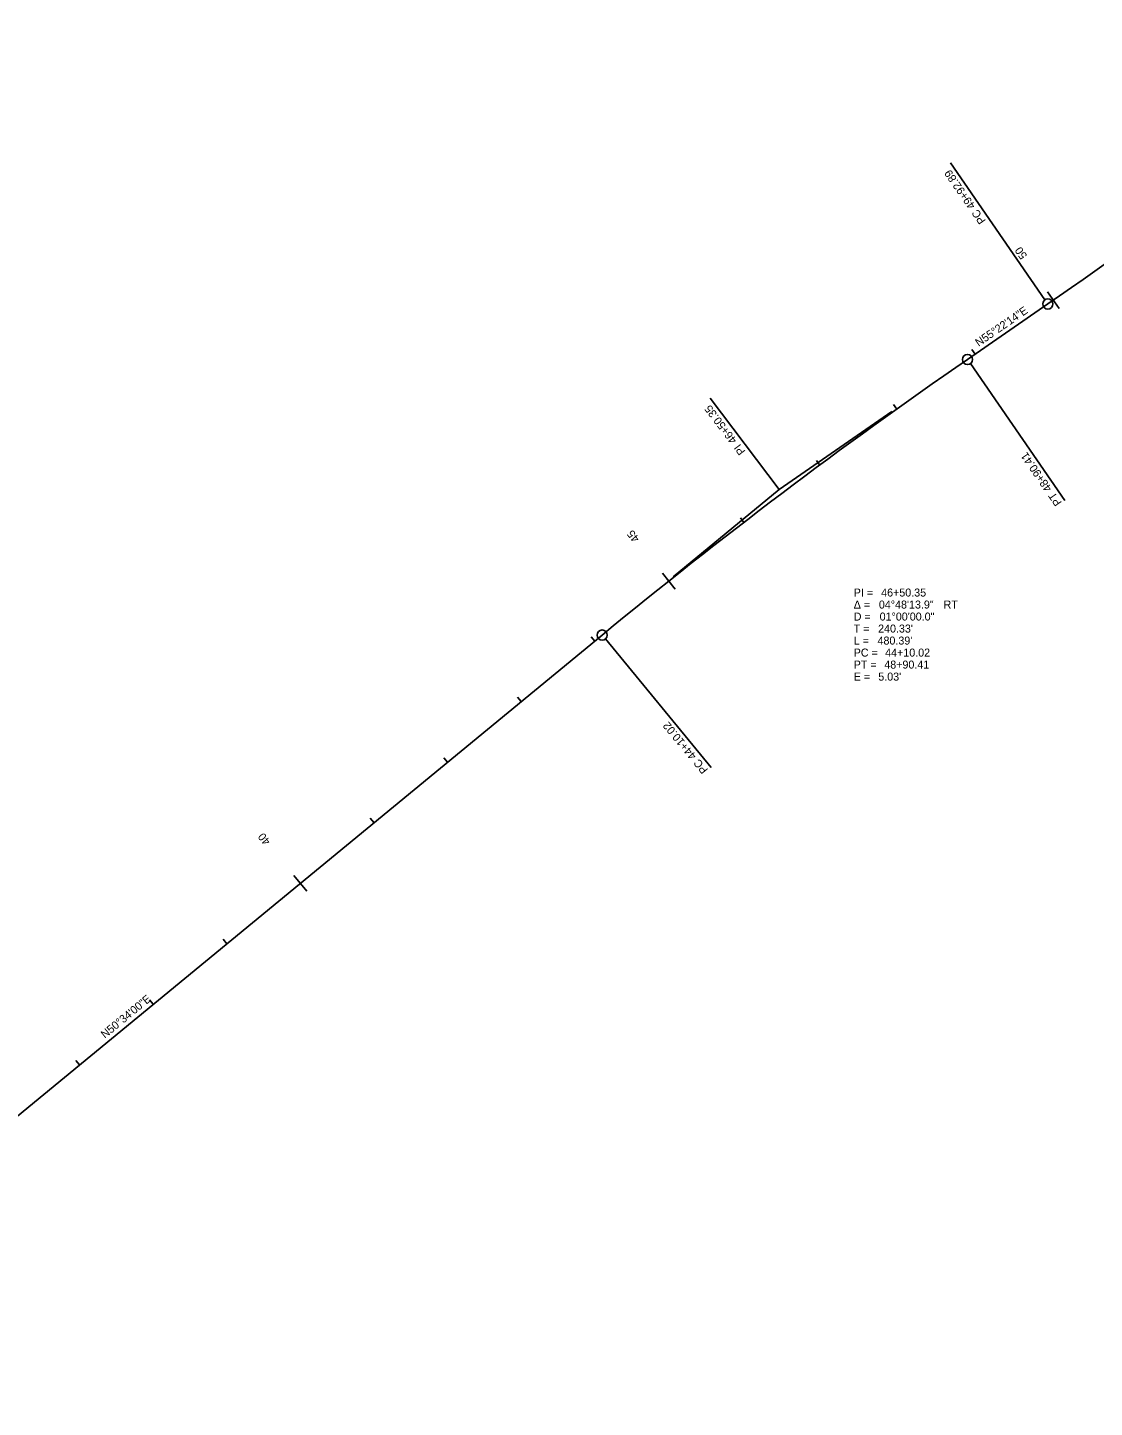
# Model space of a CAD drawing. Extents: x 1145421 to 1155673, y 2015317 to 2021442.
# Drawn here: x 1147223 to 1148342, y 2016869 to 2018317 of the extents above; entities that cross this region are included whole.
import ezdxf

# ---------------------------------------------------------------- set-up
doc = ezdxf.new("R2010")
doc.units = 0
for name, color, linetype in [('Default', 7, 'Continuous'), ('EX_CONTOUR_ANNOT_MINOR', 7, 'Continuous'), ('EX_TERRAIN', 7, 'Continuous')]:
    doc.layers.add(name, color=color, linetype=linetype)

msp = doc.modelspace()

# ---------------------------------------------------------------- linework, layer by layer
at = {"layer": 'Default'}
for p, q in [((1148208.9, 2017968.3), (1148293.2, 2018026.5)), ((1146840, 2016868.6), (1147825.5, 2017679.1))]:
    msp.add_line(p, q, dxfattribs=at)
for centre, start, end in [((1145037.3, 2022741.1), 304.62946, 309.44534), ((1151464.8, 2013253.8), 124.62946, 129.43332)]:
    msp.add_arc(centre, 5729.6, start, end, dxfattribs=at)
at = {"layer": 'EX_CONTOUR_ANNOT_MINOR'}
for p, q in [((1148290.2, 2018030.9), (1148190.9, 2018174.7)), ((1148190.9, 2018174.7), (1148190.9, 2018174.7)), ((1148293, 2018039.4), (1148305.1, 2018021.9)), ((1148293.2, 2018026.5), (1148293.2, 2018026.5)), ((1148213.4, 2017978.7), (1148216.8, 2017973.8)), ((1148208.9, 2017968.3), (1148208.9, 2017968.3)), ((1148211.9, 2017963.9), (1148311.2, 2017820.2)), ((1148011.1, 2017831.7), (1147938.9, 2017927.5)), ((1147938.9, 2017927.5), (1147938.9, 2017927.5)), ((1148011.1, 2017831.7), (1148129.6, 2017913.6)), ((1148131.4, 2017921.2), (1148134.9, 2017916.3)), ((1148050.5, 2017862.3), (1148054, 2017857.5)), ((1148011.1, 2017831.7), (1147899.9, 2017740.3)), ((1148311.2, 2017820.2), (1148311.2, 2017820.2)), ((1147970.6, 2017802.1), (1147974.2, 2017797.3)), ((1147888.8, 2017744), (1147902, 2017727.4)), ((1147814, 2017677.3), (1147817.8, 2017672.7)), ((1147825.5, 2017679.1), (1147825.5, 2017679.1)), ((1147828.9, 2017675), (1147939.8, 2017540.1)), ((1147736.7, 2017613.8), (1147740.5, 2017609.2)), ((1147659.5, 2017550.3), (1147663.3, 2017545.7)), ((1147939.8, 2017540.1), (1147939.8, 2017540.1)), ((1147582.2, 2017486.8), (1147586.1, 2017482.2)), ((1147502, 2017426.9), (1147515.5, 2017410.5)), ((1147427.8, 2017359.8), (1147431.6, 2017355.1)), ((1147350.5, 2017296.2), (1147354.4, 2017291.6)), ((1147273.3, 2017232.7), (1147277.1, 2017228.1))]:
    msp.add_line(p, q, dxfattribs=at)
for centre in [(1148293.2, 2018026.5), (1148208.9, 2017968.3), (1147825.5, 2017679.1)]:
    msp.add_circle(centre, 5.34, dxfattribs=at)
at = {"layer": 'EX_TERRAIN'}
for p, q in [((1148208.9, 2017968.3), (1148293.2, 2018026.5)), ((1146840, 2016868.6), (1147825.5, 2017679.1))]:
    msp.add_line(p, q, dxfattribs=at)
for centre, start, end in [((1145037.3, 2022741.1), 304.62946, 309.44534), ((1151464.8, 2013253.8), 124.62946, 129.43332)]:
    msp.add_arc(centre, 5729.6, start, end, dxfattribs=at)

# ---------------------------------------------------------------- texts
at = {"layer": 'EX_CONTOUR_ANNOT_MINOR'}
for s, rotation, p in [('49+92.89', 124.6295, (1148217.7, 2018129.5)), ('PC', 124.6295, (1148228.5, 2018113.9)), ('50', 124.7006, (1148272, 2018077.1)), ('N55°22\'14"E', 34.6295, (1148220.6, 2017981.5)), ('46+50.35', 127.0314, (1147967.4, 2017883.7)), ('PI ', 127.0314, (1147976.3, 2017871.9)), ('48+90.41', 124.6295, (1148297.9, 2017833)), ('PT', 124.6295, (1148308.2, 2017818.1)), ('45', 128.5335, (1147865.2, 2017780.4)), ('44+10.02', 129.4333, (1147925, 2017552.5)), ('PC', 129.4333, (1147937.1, 2017537.8)), ('40', 129.4333, (1147478, 2017462.7)), ('N50°34\'00"E', 39.4333, (1147303.7, 2017255.4))]:
    msp.add_text(s, height=8.4, rotation=rotation, dxfattribs=at).set_placement(p)
for s, p in [('PI = ', (1148089.5, 2017719.5)), ('46+50.35', (1148118.3, 2017719.5)), ('Δ = ', (1148089.5, 2017706.9)), ('04°48\'13.9"', (1148115.9, 2017706.9)), (' RT', (1148180.7, 2017706.9)), ('D = ', (1148089.5, 2017694.3)), ('01°00\'00.0"', (1148116.7, 2017694.3)), ('T = ', (1148089.5, 2017681.7)), ("240.33'", (1148115.1, 2017681.7)), ('L = ', (1148089.5, 2017669.1)), ("480.39'", (1148114.5, 2017669.1)), ('PC = ', (1148089.5, 2017656.5)), ('PT = ', (1148089.5, 2017643.9)), ('48+90.41', (1148121.6, 2017643.9)), ('44+10.02', (1148122.5, 2017656.5)), ('E = ', (1148089.5, 2017631.3)), ("5.03'", (1148115.3, 2017631.3))]:
    msp.add_text(s, height=8.4, dxfattribs=at).set_placement(p)

doc.saveas('drawing.dxf')
